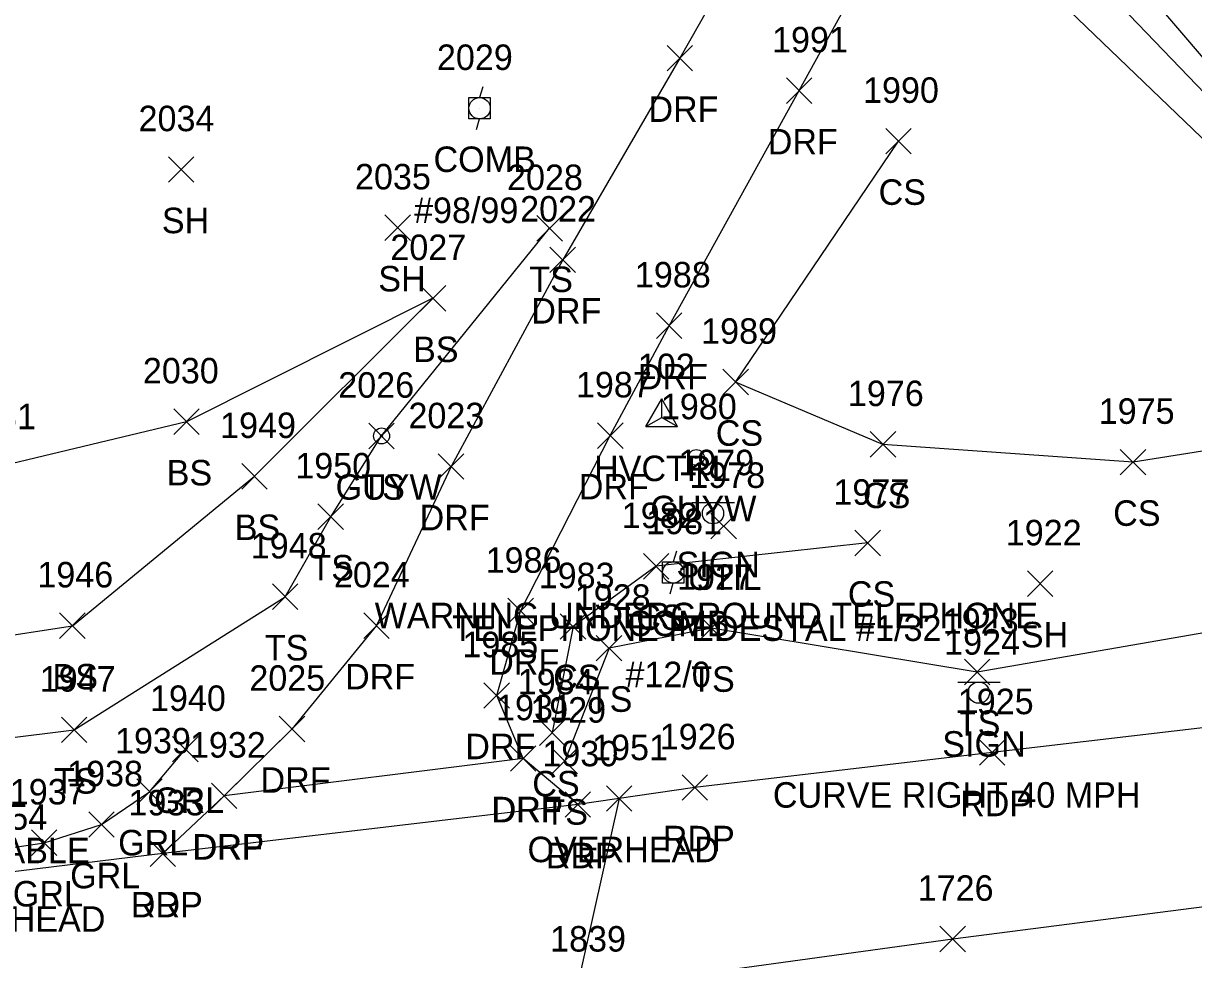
# Model space of a CAD drawing. Extents: x 1600395 to 1603269, y 874955 to 877143.
# Drawn here: x 1601910.3 to 1602002, y 875263.7 to 875337.1 of the extents above; entities that cross this region are included whole.
import ezdxf

# ---------------------------------------------------------------- set-up
doc = ezdxf.new("R2010")
doc.units = 0
for name, color, linetype in [('C_A', 7, 'Continuous'), ('C_I', 7, 'Continuous'), ('CPSM', 7, 'Continuous'), ('L_A', 7, 'Continuous'), ('L_I', 7, 'Continuous'), ('L_TIC', 7, 'Continuous'), ('LELB', 7, 'Continuous'), ('P_A', 7, 'Continuous'), ('P_I', 7, 'Continuous'), ('P_TIC', 7, 'Continuous'), ('PET', 7, 'Continuous'), ('PRC', 7, 'Continuous'), ('R_A', 7, 'Continuous'), ('R_I', 7, 'Continuous'), ('R_TIC', 7, 'Continuous'), ('RDF', 7, 'Continuous'), ('RDP', 7, 'Continuous'), ('RGR', 7, 'Continuous'), ('S_A', 7, 'Continuous'), ('S_C', 7, 'Continuous'), ('S_I', 7, 'Continuous'), ('SSGN', 7, 'Continuous'), ('U_A', 7, 'Continuous'), ('U_C', 7, 'Continuous'), ('U_I', 7, 'Continuous'), ('U_TIC', 7, 'Continuous'), ('UCO', 7, 'Continuous'), ('UDEFAULT', 7, 'Continuous'), ('UP', 7, 'Continuous'), ('UPGW', 7, 'Continuous')]:
    doc.layers.add(name, color=color, linetype=linetype)

msp = doc.modelspace()

# ---------------------------------------------------------------- linework, layer by layer
at = {"layer": 'CPSM'}
for p, q in [((1601959.094, 875305.492), (1601960.344, 875307.657)), ((1601961.594, 875305.492), (1601960.344, 875307.657)), ((1601960.345, 875306.213), (1601960.344, 875307.657)), ((1601959.094, 875305.492), (1601960.345, 875306.213)), ((1601960.345, 875306.213), (1601960.345, 875306.213)), ((1601960.345, 875306.213), (1601961.594, 875305.492)), ((1601959.094, 875305.492), (1601961.594, 875305.492))]:
    msp.add_line(p, q, dxfattribs=at)
at = {"layer": 'L_TIC'}
for points in [[(1601977.909, 875326.882), (1601979.909, 875328.882)], [(1601979.909, 875326.882), (1601977.909, 875328.882)], [(1601921.661, 875324.658), (1601923.661, 875326.658)], [(1601923.661, 875324.658), (1601921.661, 875326.658)], [(1601938.634, 875320.093), (1601940.634, 875322.093)], [(1601940.634, 875320.093), (1601938.634, 875322.093)], [(1601950.556, 875320.042), (1601952.556, 875322.042)], [(1601952.556, 875320.042), (1601950.556, 875322.042)], [(1601941.406, 875314.551), (1601943.406, 875316.551)], [(1601943.406, 875314.551), (1601941.406, 875316.551)], [(1601965.138, 875307.985), (1601967.138, 875309.985)], [(1601967.138, 875307.985), (1601965.138, 875309.985)], [(1601922.087, 875304.876), (1601924.087, 875306.876)], [(1601924.087, 875304.876), (1601922.087, 875306.876)], [(1601937.378, 875303.757), (1601939.378, 875305.757)], [(1601939.378, 875303.757), (1601937.378, 875305.757)], [(1601976.689, 875303.097), (1601978.689, 875305.097)], [(1601978.689, 875303.097), (1601976.689, 875305.097)], [(1601996.301, 875301.707), (1601998.301, 875303.707)], [(1601998.301, 875301.707), (1601996.301, 875303.707)], [(1601927.42, 875300.595), (1601929.42, 875302.595)], [(1601929.42, 875300.595), (1601927.42, 875302.595)], [(1601933.39, 875297.423), (1601935.39, 875299.423)], [(1601935.39, 875297.423), (1601933.39, 875299.423)], [(1601975.496, 875295.362), (1601977.496, 875297.362)], [(1601977.496, 875295.362), (1601975.496, 875297.362)], [(1601958.907, 875293.532), (1601960.907, 875295.532)], [(1601960.907, 875293.532), (1601958.907, 875295.532)], [(1601989.014, 875292.177), (1601991.014, 875294.177)], [(1601991.014, 875292.177), (1601989.014, 875294.177)], [(1601929.815, 875291.149), (1601931.815, 875293.149)], [(1601931.815, 875291.149), (1601929.815, 875293.149)], [(1601913.133, 875288.877), (1601915.133, 875290.877)], [(1601915.133, 875288.877), (1601913.133, 875290.877)], [(1601952.391, 875288.817), (1601954.391, 875290.817)], [(1601954.391, 875288.817), (1601952.391, 875290.817)], [(1601963.247, 875288.689), (1601965.247, 875290.689)], [(1601965.247, 875288.689), (1601963.247, 875290.689)], [(1601955.216, 875287.119), (1601957.216, 875289.119)], [(1601957.216, 875287.119), (1601955.216, 875289.119)], [(1601984.078, 875285.238), (1601986.078, 875287.238)], [(1601986.078, 875285.238), (1601984.078, 875287.238)], [(1601913.27, 875280.705), (1601915.27, 875282.705)], [(1601915.27, 875280.705), (1601913.27, 875282.705)], [(1601950.754, 875280.487), (1601952.754, 875282.487)], [(1601952.754, 875280.487), (1601950.754, 875282.487)], [(1601951.736, 875278.27), (1601953.736, 875280.27)], [(1601953.736, 875278.27), (1601951.736, 875280.27)]]:
    msp.add_lwpolyline(points, dxfattribs=at)
at = {"layer": 'LELB'}
for points in [[(1602130.81, 875321.995), (1602086.811, 875321.908), (1602044.285, 875322.579), (1602008.888, 875327.294), (1601983.723, 875356.75), (1601975.467, 875363.358), (1601927.656, 875400.898)], [(1602174.044, 875317.39), (1602130.358, 875320.318), (1602087.226, 875319.39), (1602042.601, 875319.821), (1602008.236, 875326.09), (1601982.496, 875352.908), (1601973.752, 875359.576), (1601926.726, 875398.957)], [(1602129.738, 875318.211), (1602087.657, 875317.408), (1602041.946, 875317.605), (1602007.813, 875323.215), (1601980.703, 875349.267), (1601972.052, 875352.536), (1601923.263, 875397.154)], [(1602130.114, 875313.965), (1602085.406, 875312.984), (1602041.79, 875309.762), (1601997.301, 875302.707), (1601977.689, 875304.097), (1601966.138, 875308.985), (1601978.909, 875327.882)], [(1601889.866, 875276.261), (1601896.825, 875279.531), (1601914.27, 875281.705), (1601930.815, 875292.149), (1601934.39, 875298.423), (1601938.378, 875304.757), (1601951.556, 875321.042)], [(1601884.023, 875279.819), (1601895.255, 875286.952), (1601914.133, 875289.877), (1601928.42, 875301.595), (1601942.406, 875315.551), (1601923.087, 875305.876), (1601908.098, 875302.283)], [(1602400.485, 875294.366), (1602361.786, 875296.793), (1602320.067, 875299.514), (1602288.685, 875301.158), (1602257.591, 875301.181), (1602210.361, 875302.473), (1602169.509, 875304.242), (1602128.15, 875302.207), (1602094.954, 875298.421), (1602055.202, 875294.7), (1602015.808, 875291.561), (1601985.078, 875286.238), (1601964.247, 875289.689), (1601956.216, 875288.119), (1601952.736, 875279.27)], [(1601976.496, 875296.362), (1601959.907, 875294.532), (1601953.391, 875289.817), (1601951.754, 875281.487)]]:
    msp.add_lwpolyline(points, dxfattribs=at)
at = {"layer": 'P_TIC'}
for points in [[(1601985.251, 875278.934), (1601987.251, 875280.934)], [(1601987.251, 875278.934), (1601985.251, 875280.934)], [(1601961.937, 875276.18), (1601963.937, 875278.18)], [(1601963.937, 875276.18), (1601961.937, 875278.18)], [(1601952.765, 875274.849), (1601954.765, 875276.849)], [(1601954.765, 875274.849), (1601952.765, 875276.849)], [(1601920.228, 875270.998), (1601922.228, 875272.998)], [(1601922.228, 875270.998), (1601920.228, 875272.998)], [(1601982.161, 875264.299), (1601984.161, 875266.299)], [(1601984.161, 875264.299), (1601982.161, 875266.299)]]:
    msp.add_lwpolyline(points, dxfattribs=at)
at = {"layer": 'PET'}
msp.add_lwpolyline([(1602400.31, 875290.463), (1602361.622, 875292.913), (1602320.007, 875295.059), (1602288.497, 875296.291), (1602257.257, 875296.749), (1602210.132, 875296.364), (1602169.383, 875295.49), (1602128.802, 875293.683), (1602096.324, 875291.616), (1602056.865, 875287.915), (1602018.574, 875283.709), (1601986.251, 875279.934), (1601962.937, 875277.18), (1601953.765, 875275.849), (1601921.228, 875271.998), (1601886.385, 875267.749)], dxfattribs=at)
at = {"layer": 'PRC'}
msp.add_lwpolyline([(1602402.71, 875276.764), (1602360.412, 875278.936), (1602318.065, 875280.962), (1602289.167, 875282.155), (1602257.665, 875282.807), (1602210.34, 875282.997), (1602169.349, 875282.18), (1602129.851, 875280.431), (1602107.169, 875278.743), (1602075.284, 875276.038), (1602025.434, 875270.724), (1601983.161, 875265.299), (1601954.295, 875261.316), (1601930.368, 875258.058), (1601901.661, 875254.25), (1601879.639, 875251.364)], dxfattribs=at)
at = {"layer": 'R_TIC'}
for points in [[(1601960.766, 875333.387), (1601962.766, 875335.387)], [(1601962.766, 875333.387), (1601960.766, 875335.387)], [(1601970.122, 875330.838), (1601972.122, 875332.838)], [(1601972.122, 875330.838), (1601970.122, 875332.838)], [(1601951.581, 875317.571), (1601953.581, 875319.571)], [(1601953.581, 875317.571), (1601951.581, 875319.571)], [(1601959.932, 875312.404), (1601961.932, 875314.404)], [(1601961.932, 875312.404), (1601959.932, 875314.404)], [(1601955.309, 875303.783), (1601957.309, 875305.783)], [(1601957.309, 875303.783), (1601955.309, 875305.783)], [(1601942.825, 875301.36), (1601944.825, 875303.36)], [(1601944.825, 875301.36), (1601942.825, 875303.36)], [(1601948.281, 875290.024), (1601950.281, 875292.024)], [(1601950.281, 875290.024), (1601948.281, 875292.024)], [(1601936.979, 875288.879), (1601938.979, 875290.879)], [(1601938.979, 875288.879), (1601936.979, 875290.879)], [(1601946.406, 875283.404), (1601948.406, 875285.404)], [(1601948.406, 875283.404), (1601946.406, 875285.404)], [(1601930.35, 875280.769), (1601932.35, 875282.769)], [(1601932.35, 875280.769), (1601930.35, 875282.769)], [(1601930.35, 875280.769), (1601932.35, 875282.769)], [(1601932.35, 875280.769), (1601930.35, 875282.769)], [(1601921.997, 875279.19), (1601923.997, 875281.19)], [(1601923.997, 875279.19), (1601921.997, 875281.19)], [(1601948.481, 875278.458), (1601950.481, 875280.458)], [(1601950.481, 875278.458), (1601948.481, 875280.458)], [(1601948.481, 875278.458), (1601950.481, 875280.458)], [(1601950.481, 875278.458), (1601948.481, 875280.458)], [(1601919.18, 875275.857), (1601921.18, 875277.857)], [(1601921.18, 875275.857), (1601919.18, 875277.857)], [(1601925.041, 875275.529), (1601927.041, 875277.529)], [(1601927.041, 875275.529), (1601925.041, 875277.529)], [(1601925.041, 875275.529), (1601927.041, 875277.529)], [(1601927.041, 875275.529), (1601925.041, 875277.529)], [(1601952.765, 875274.849), (1601954.765, 875276.849)], [(1601954.765, 875274.849), (1601952.765, 875276.849)], [(1601915.415, 875273.279), (1601917.415, 875275.279)], [(1601917.415, 875273.279), (1601915.415, 875275.279)], [(1601910.924, 875271.854), (1601912.924, 875273.854)], [(1601912.924, 875271.854), (1601910.924, 875273.854)], [(1601920.228, 875270.998), (1601922.228, 875272.998)], [(1601922.228, 875270.998), (1601920.228, 875272.998)]]:
    msp.add_lwpolyline(points, dxfattribs=at)
at = {"layer": 'RDF'}
for points in [[(1602061.844, 875684.018), (1602044.241, 875629.479), (1602032.842, 875584.978), (1602023.304, 875548.954), (1602011.203, 875500.699), (1601997.923, 875449.957), (1601988.661, 875414.529), (1601981.095, 875381.42), (1601975.467, 875363.358), (1601973.752, 875359.576), (1601972.052, 875352.536), (1601961.766, 875334.387), (1601952.581, 875318.571), (1601943.825, 875302.36), (1601937.979, 875289.879), (1601931.35, 875281.769)], [(1601949.481, 875279.458), (1601947.406, 875284.404), (1601949.281, 875291.024), (1601956.309, 875304.783), (1601960.932, 875313.404), (1601971.122, 875331.838), (1601980.703, 875349.267), (1601982.496, 875352.908), (1601983.723, 875356.75), (1601986.103, 875362.37), (1601988.197, 875377.056), (1601992.914, 875398.509), (1602001.449, 875435.574), (1602010.573, 875469.717), (1602020.944, 875507.945), (1602032.385, 875553.275), (1602043.325, 875596.715), (1602063.594, 875669.347)], [(1601926.041, 875276.529), (1601931.35, 875281.769)]]:
    msp.add_lwpolyline(points, dxfattribs=at)
at = {"layer": 'RDP'}
msp.add_lwpolyline([(1601953.765, 875275.849), (1601949.481, 875279.458), (1601926.041, 875276.529), (1601921.228, 875271.998)], dxfattribs=at)
at = {"layer": 'RGR'}
msp.add_lwpolyline([(1601888.572, 875269.39), (1601911.924, 875272.854), (1601916.415, 875274.279), (1601920.18, 875276.857), (1601922.997, 875280.19)], dxfattribs=at)
at = {"layer": 'SSGN'}
for p, q in [((1601962.718, 875299.53), (1601966.052, 875299.53)), ((1601964.365, 875298.696), (1601964.365, 875298.696)), ((1601983.558, 875285.457), (1601986.891, 875285.457)), ((1601985.205, 875284.623), (1601985.205, 875284.623))]:
    msp.add_line(p, q, dxfattribs=at)
for centre in [(1601964.365, 875298.696), (1601985.205, 875284.623)]:
    msp.add_circle(centre, 0.833, dxfattribs=at)
at = {"layer": 'U_TIC'}
for points in [[(1601956.011, 875275.328), (1601958.011, 875277.328)], [(1601958.011, 875275.328), (1601956.011, 875277.328)]]:
    msp.add_lwpolyline(points, dxfattribs=at)
at = {"layer": 'UCO'}
msp.add_lwpolyline([(1601957.011, 875276.328), (1601943.723, 875216.832)], dxfattribs=at)
at = {"layer": 'UDEFAULT'}
for points in [[(1601964.204, 875296.682), (1601966.204, 875298.682)], [(1601966.204, 875296.682), (1601964.204, 875298.682)]]:
    msp.add_lwpolyline(points, dxfattribs=at)
at = {"layer": 'UP'}
for p, q in [((1601946.315, 875332.126), (1601946.065, 875331.292)), ((1601945.232, 875329.626), (1601945.232, 875331.292)), ((1601945.232, 875331.292), (1601946.899, 875331.292)), ((1601946.899, 875331.292), (1601946.899, 875329.626)), ((1601946.899, 875329.626), (1601945.232, 875329.626)), ((1601945.815, 875328.793), (1601946.065, 875329.626)), ((1601946.065, 875330.459), (1601946.065, 875330.459)), ((1601961.5, 875295.721), (1601961.25, 875294.887)), ((1601960.416, 875293.221), (1601960.416, 875294.887)), ((1601960.416, 875294.887), (1601962.083, 875294.887)), ((1601962.083, 875294.887), (1601962.083, 875293.221)), ((1601961.25, 875294.054), (1601961.25, 875294.054)), ((1601962.083, 875293.221), (1601960.416, 875293.221)), ((1601961, 875292.387), (1601961.25, 875293.221))]:
    msp.add_line(p, q, dxfattribs=at)
for centre in [(1601946.065, 875330.459), (1601961.25, 875294.054)]:
    msp.add_circle(centre, 0.833, dxfattribs=at)
at = {"layer": 'UPGW'}
for centre, radius in [((1601938.378, 875304.757), 0.625), ((1601938.378, 875304.757), 0.0833), ((1601963.057, 875303.067), 0.625), ((1601963.057, 875303.067), 0.0833)]:
    msp.add_circle(centre, radius, dxfattribs=at)

# ---------------------------------------------------------------- texts
at = {"layer": 'C_A'}
msp.add_text('HVCTRL', height=2, dxfattribs=at).set_placement((1601955.038, 875301.213))
at = {"layer": 'C_I'}
msp.add_text('102', height=2, dxfattribs=at).set_placement((1601958.471, 875309.213))
at = {"layer": 'L_A'}
for s, p in [('CS', (1601977.35, 875322.882)), ('SH', (1601921.149, 875320.658)), ('SH', (1601938.122, 875316.093)), ('TS', (1601949.965, 875316.042)), ('BS', (1601940.847, 875310.551)), ('CS', (1601964.579, 875303.985)), ('BS', (1601921.528, 875300.876)), ('TS', (1601936.788, 875299.757)), ('CS', (1601976.13, 875299.097)), ('CS', (1601995.742, 875297.707)), ('BS', (1601926.861, 875296.595)), ('TS', (1601932.8, 875293.423)), ('CS', (1601974.937, 875291.362)), ('CS', (1601958.348, 875289.532)), ('SH', (1601988.502, 875288.177)), ('TS', (1601929.225, 875287.149)), ('BS', (1601912.574, 875284.877)), ('CS', (1601951.832, 875284.817)), ('TS', (1601962.656, 875284.689)), ('TS', (1601954.625, 875283.119)), ('TS', (1601983.487, 875281.238)), ('TS', (1601912.679, 875276.705)), ('CS', (1601950.195, 875276.487)), ('TS', (1601951.146, 875274.27))]:
    msp.add_text(s, height=2, dxfattribs=at).set_placement(p)
at = {"layer": 'L_I'}
for s, p in [('1990', (1601976.13, 875330.882)), ('2034', (1601919.323, 875328.658)), ('2035', (1601936.295, 875324.093)), ('2028', (1601948.217, 875324.042)), ('2027', (1601939.068, 875318.551)), ('1989', (1601963.438, 875311.985)), ('2030', (1601919.662, 875308.876)), ('2026', (1601934.984, 875307.757)), ('1976', (1601974.941, 875307.097)), ('1975', (1601994.608, 875305.707)), ('2031', (1601905.327, 875305.283)), ('1949', (1601925.72, 875304.595)), ('1950', (1601931.611, 875301.423)), ('1977', (1601973.803, 875299.362)), ('1982', (1601957.214, 875297.532)), ('1922', (1601987.321, 875296.177)), ('1948', (1601928.123, 875295.149)), ('1946', (1601911.386, 875292.877)), ('1983', (1601950.698, 875292.817)), ('1927', (1601961.554, 875292.689)), ('1928', (1601953.523, 875291.119)), ('1923', (1601982.385, 875289.238)), ('1947', (1601911.577, 875284.705)), ('1984', (1601949.062, 875284.487)), ('1929', (1601950.036, 875282.27))]:
    msp.add_text(s, height=2, dxfattribs=at).set_placement(p)
at = {"layer": 'P_A'}
for p in [(1601983.739, 875274.934), (1601960.426, 875272.18), (1601951.253, 875270.849), (1601918.716, 875266.998)]:
    msp.add_text('RDP', height=2, dxfattribs=at).set_placement(p)
at = {"layer": 'P_I'}
for s, p in [('1925', (1601983.558, 875282.934)), ('1926', (1601960.19, 875280.18)), ('1930', (1601950.985, 875278.849)), ('1933', (1601918.535, 875274.998)), ('1726', (1601980.413, 875268.299)), ('1839', (1601951.594, 875264.316))]:
    msp.add_text(s, height=2, dxfattribs=at).set_placement(p)
at = {"layer": 'R_A'}
for s, p in [('DRF', (1601959.302, 875329.387)), ('DRF', (1601968.658, 875326.838)), ('DRF', (1601950.116, 875313.571)), ('DRF', (1601958.468, 875308.404)), ('DRF', (1601953.844, 875299.783)), ('DRF', (1601941.36, 875297.36)), ('DRF', (1601946.817, 875286.024)), ('DRF', (1601935.515, 875284.879)), ('DRF', (1601944.941, 875279.404)), ('DRF', (1601928.885, 875276.769)), ('DRF', (1601928.885, 875276.769)), ('GRL', (1601920.54, 875275.19)), ('DRP', (1601946.969, 875274.458)), ('DRF', (1601947.016, 875274.458)), ('GRL', (1601917.723, 875271.857)), ('DRP', (1601923.53, 875271.529)), ('DRF', (1601923.577, 875271.529)), ('DRP', (1601951.253, 875270.849)), ('GRL', (1601913.958, 875269.279)), ('GRL', (1601909.467, 875267.854)), ('DRP', (1601918.716, 875266.998))]:
    msp.add_text(s, height=2, dxfattribs=at).set_placement(p)
at = {"layer": 'R_I'}
for s, p in [('1991', (1601968.996, 875334.838)), ('2022', (1601949.242, 875321.571)), ('1988', (1601958.24, 875316.404)), ('1987', (1601953.616, 875307.783)), ('2023', (1601940.486, 875305.36)), ('1986', (1601946.534, 875294.024)), ('2024', (1601934.641, 875292.879)), ('1985', (1601944.713, 875287.404)), ('2025', (1601928.011, 875284.769)), ('2025', (1601928.011, 875284.769)), ('1940', (1601920.218, 875283.19)), ('1931', (1601947.355, 875282.458)), ('1931', (1601947.355, 875282.458)), ('1939', (1601917.48, 875279.857)), ('1932', (1601923.349, 875279.529)), ('1932', (1601923.349, 875279.529)), ('1930', (1601950.985, 875278.849)), ('1938', (1601913.722, 875277.279)), ('1937', (1601909.231, 875275.854)), ('1933', (1601918.535, 875274.998))]:
    msp.add_text(s, height=2, dxfattribs=at).set_placement(p)
at = {"layer": 'S_A'}
for p in [(1601961.503, 875293.676), (1601982.343, 875279.603)]:
    msp.add_text('SIGN', height=2, dxfattribs=at).set_placement(p)
at = {"layer": 'S_C'}
for s, p in [('WARNING UNDERGROUND TELEPHONE', (1601937.842, 875289.676)), ('CURVE RIGHT 40 MPH', (1601969.06, 875275.603)), ('CAUTION FIBER OPTIC CABLE', (1601876.41, 875271.244))]:
    msp.add_text(s, height=2, dxfattribs=at).set_placement(p)
at = {"layer": 'S_I'}
for s, p in [('1979', (1601961.645, 875301.676)), ('1924', (1601982.493, 875287.603))]:
    msp.add_text(s, height=2, dxfattribs=at).set_placement(p)
at = {"layer": 'U_A'}
for s, p in [('COMB', (1601942.451, 875325.459)), ('GUYW', (1601934.772, 875299.757)), ('GUYW', (1601959.451, 875298.067)), ('UTIL', (1601962.369, 875292.682)), ('COMB', (1601957.635, 875289.054)), ('OVERHEAD', (1601949.822, 875271.328)), ('OVERHEAD', (1601901.718, 875265.872))]:
    msp.add_text(s, height=2, dxfattribs=at).set_placement(p)
at = {"layer": 'U_C'}
for s, p in [('#98/99', (1601940.924, 875321.459)), ('TELEPHONE PEDESTAL #1/32', (1601943.929, 875288.682)), ('#12/0', (1601957.494, 875285.054))]:
    msp.add_text(s, height=2, dxfattribs=at).set_placement(p)
at = {"layer": 'U_I'}
for s, p in [('2029', (1601942.719, 875333.459)), ('2026', (1601934.984, 875307.757)), ('1980', (1601960.278, 875306.067)), ('1978', (1601962.511, 875300.682)), ('1981', (1601959.124, 875297.054)), ('1951', (1601954.885, 875279.328)), ('1954', (1601906.214, 875273.872))]:
    msp.add_text(s, height=2, dxfattribs=at).set_placement(p)

doc.saveas('drawing.dxf')
